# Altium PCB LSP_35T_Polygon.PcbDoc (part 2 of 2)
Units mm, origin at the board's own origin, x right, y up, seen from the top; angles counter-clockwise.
Board outline 152.4 x 101.6 mm, 4 copper layers (Top Layer, Mid-Layer 1, Mid-Layer 3, Bottom Layer); 138 components, 96 nets, 424 pads, 124 vias.
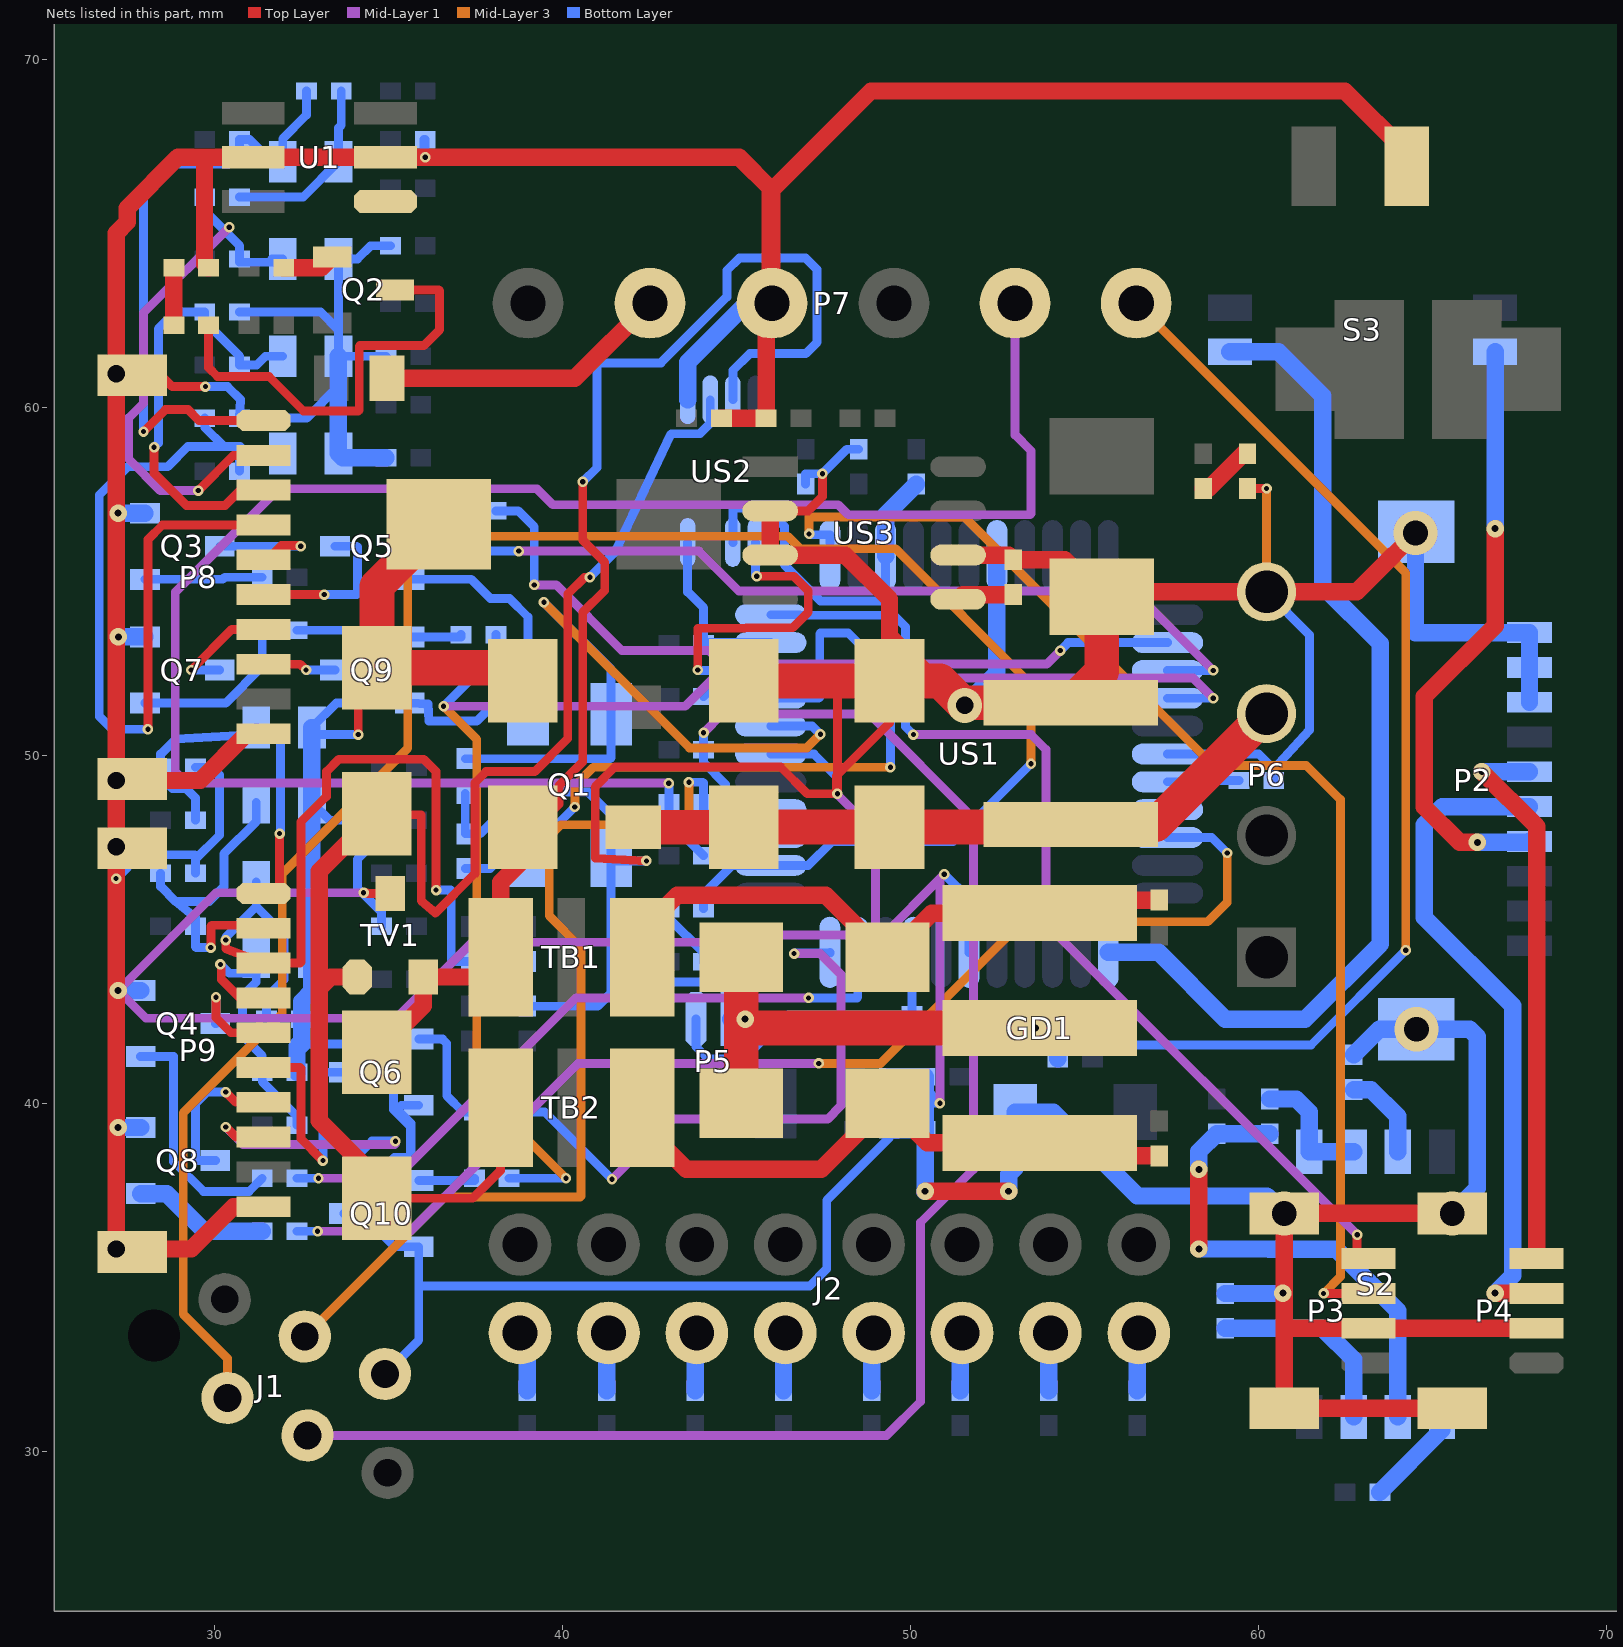
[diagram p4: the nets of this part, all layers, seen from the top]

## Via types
v1: diameter 0.3, hole 0.15, Top Layer to Bottom Layer, tented both sides, 95 vias
v2: diameter 0.5, hole 0.2, Top Layer to Bottom Layer, tented both sides, 20 vias
v3: diameter 1, hole 0.5, Top Layer to Bottom Layer, tented both sides, 5 vias
v4: diameter 1.27, hole 0.711, Top Layer to Bottom Layer, tented both sides, 4 vias

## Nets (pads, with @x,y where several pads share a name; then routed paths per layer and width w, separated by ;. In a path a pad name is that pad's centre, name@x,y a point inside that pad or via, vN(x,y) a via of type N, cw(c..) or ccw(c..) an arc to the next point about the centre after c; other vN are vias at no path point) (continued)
DO2: R34.2 US1.24 | length 22.4
  Mid-Layer 1 w0.254: v1(39.192,54.897) 39.826,54.897 41.714,53.01 44.222,53.01 44.611,52.621 53.916,52.621 v1(54.305,53.01)
  Bottom Layer w0.254: R34.2@38.092,57.023 38.735,57.023 39.192,56.566 v1(39.192,54.897) ; v1(54.305,53.01) 54.533,53.238 US1.24@57.389,53.238
DO3: R40.2 US1.25 | length 31
  Mid-Layer 1 w0.254: v1(38.748,55.867) 43.926,55.867 45.077,54.716 56.427,54.716 v1(58.706,52.438)
  Bottom Layer w0.254: R40.2@32.377,53.594 34.536,53.594 34.917,53.975 34.917,55.601 35.184,55.867 v1(38.748,55.867) ; US1.25@57.389,52.438 v1(58.706,52.438)
DO4: R46.2 R47.2 US1.26 | length 43.3
  Mid-Layer 1 w0.254: v1(36.589,51.41) 43.532,51.41 44.339,52.217 58.124,52.217 v1(58.703,51.638)
  Mid-Layer 3 w0.254: v1(36.589,51.41) 37.541,50.457 37.541,40.411 v1(40.107,37.846)
  Bottom Layer w0.254: v1(36.589,51.41) 38.092,52.913 R46.2@38.092,53.467 ; R47.2@38.473,37.846 v1(40.107,37.846) ; US1.26@57.389,51.638 v1(58.703,51.638)
DO5: R33.2 US1.43 | length 19.6
  Mid-Layer 1 w0.254: v1(32.995,37.846) 35.204,37.846 40.386,43.028 v1(47.075,43.028)
  Bottom Layer w0.254: R33.2@32.377,37.846 v1(32.995,37.846) ; v1(47.075,43.028) 48.464,43.028 48.489,43.053 US1.43@48.489,44.338
DO6: R36.2 US1.44 | length 17.6
  Mid-Layer 1 w0.254: v1(41.427,37.821) 43.155,39.548 47.625,39.548 48.006,39.929 48.006,43.709 47.411,44.303 v1(46.66,44.303)
  Bottom Layer w0.254: R36.2@38.473,39.751 39.497,39.751 v1(41.427,37.821) ; v1(46.66,44.303) 46.68,44.323 47.689,44.323 US1.44@47.689,44.338
DO7: R41.2 US1.31 | length 34
  Mid-Layer 1 w0.254: v1(32.969,36.322) 35.636,36.322 40.462,41.148 v1(47.371,41.148)
  Mid-Layer 3 w0.254: v1(47.371,41.148) 49.149,41.148 53.216,45.215 58.547,45.215 59.106,45.774 v1(59.106,47.193)
  Bottom Layer w0.254: R41.2@32.377,36.322 v1(32.969,36.322) ; US1.31@57.389,47.638 58.661,47.638 v1(59.106,47.193)
DO8: US1.30
GND: C1.2 C2.1 C3.1 C4.2 C5.2 C7.1 C9.1 C10.1 C11.2 C12.1 C13.2 C14.1 C15.1 C16.1 C17.1 C18.1 C19.1 C20.1 C21.1 C22.1 C23.1 C24.1 C25.1 C26.1 C27.1 C28.1 C29.1 CGND.1 D1.1 D2.2 D4.1 D6.1 D7.1 D8.1 D9.1 D10.1 D11.1 D12.1 D13.1 D14.1 D15.1 G1.2 GD1.3 J1.5 LED2.2 LED3.2 P2.8 P2.9 P2.10 P2.11 P2.12 P3.2 P3.Z1 P3.Z2 P4.2 P4.Z1 P4.Z2 P5.2 P6.4 P7.3 P8.10 P8.Z1 P8.Z2 P9.10 P9.Z1 P9.Z2 Q1.GND Q3.2 Q4.2 Q5.2 Q6.2 Q7.2 Q8.2 Q9.2 Q10.2 R7.1 R16.2 R17.2 R21.2 RGND.1 T1.2 TI1.2 TI2.2 TV1.3 U1.2 U1.5 US1.6 US1.18 US1.28 US1.39 US2.5 US3.2 US3.3 US3.6 | length 522
  Top Layer w0.254: 27.178,64.643 v3(27.178,60.96) 27.178,53.401 v3(27.178,49.276) v3(27.178,47.371) v1(27.178,46.457) 27.178,43.548 27.178,43.409 27.178,43.277 27.178,39.365 v2(27.239,39.304) ; v2@27.203,43.277 27.203,46.457 27.203,47.329 P9.Z1@27.645,47.329 ; v2(27.239,56.957) 27.203,56.993 27.203,60.918 P8.Z1@27.645,60.918 ; v2(27.244,53.401) 27.241,53.401 27.229,53.388 27.229,49.318 P8.Z2@27.645,49.318 ; P9.Z2@27.645,35.729 P9.Z2@28.118,35.729 ; P8.Z1@28.219,61.166 28.791,60.594 v1(29.743,60.594) ; 28.219,66.446 28.956,67.183 29.718,67.183 U1.5@31.12,67.183 U1.2@34.92,67.183 v1(36.06,67.183) 44.915,67.183 45.855,66.243 45.855,62.822 C9.1@45.855,59.69 ; 30.552,37.029 P9.10@31.42,37.029 ; v1(34.138,50.597) 34.138,51.752 34.523,52.138 D4.1@38.862,52.138 ; v1(34.29,46.05) 34.392,46.05 v1@34.411,46.031 ; v1@34.392,46.031 v1@34.411,46.031 ; TV1.3@35.052,46.031 v1@34.411,46.031 ; v1(42.418,46.965) 40.945,47.041 40.945,49.098 41.512,49.665 46.271,49.665 47.041,48.895 v1(47.904,48.895) 47.904,49.433 ; TI1.2@45.144,44.196 45.144,42.53 v2(45.256,42.418) ; D6.1@45.212,52.138 47.625,52.138 47.904,51.859 47.904,49.433 ; US3.2@45.974,57.023 47.066,57.023 47.473,57.429 v1(47.473,58.09) ; v1@47.879,48.895 47.879,49.408 47.904,49.433 ; 49.403,53.594 50.859,52.138 51.486,51.511 v3(51.562,51.435) ; 49.403,54.483 T1.2@49.403,52.138 49.403,50.932 47.904,49.433 ; LED2.2@59.69,57.666 v1(60.237,57.666) ; P3.Z1@60.745,31.236 60.745,33.528 60.753,33.536
  Top Layer w0.5: LED3.2@29.837,64.008 29.718,64.127 29.718,67.183 ; P9.10@31.42,37.029 30.552,37.029 29.337,35.814 v3(27.178,35.814) v3(27.178,47.371) v3(27.178,49.276) ; P8.10@31.42,50.618 30.933,50.618 29.591,49.276 v3(27.178,49.276) ; C10.1@44.569,59.69 C9.1@45.855,59.69 45.855,62.822 P7.3@46.025,62.992 46.025,66.243 ; US3.2@45.974,57.023 US3.3@45.974,55.753 48.133,55.753 49.403,54.483 T1.2@49.403,52.138 ; v2(50.427,37.473) v2(52.824,37.473) ; US3.6@51.374,55.753 52.824,55.753 C12.1@52.959,55.618 54.44,55.618 D7.1@55.499,54.559 55.636,54.697 P6.4@60.237,54.697 62.825,54.697 63.348,55.22 v4(64.516,56.388) ; 60.753,33.536 P3.2@63.17,33.536 P4.2@67.996,33.536 ; C13.2@64.262,66.929 64.262,67.31 62.484,69.088 48.87,69.088 46.025,66.243 ; P4.Z1@65.571,31.236 P3.Z1@60.745,31.236 v4(60.745,36.836) v4(65.571,36.836) ; v3(27.178,49.276) 27.178,53.401 v3(27.178,60.96) 27.178,65.006 27.497,65.324 27.497,65.724 28.956,67.183 29.718,67.183 ; 29.718,67.183 U1.5@31.12,67.183 U1.2@34.92,67.183 45.085,67.183 46.025,66.243
  Top Layer w1: C11.2@36.453,56.642 34.671,54.86 D2.2@34.671,52.519 38.481,52.519 D4.1@38.862,52.138 ; TI2.2@45.144,40.005 v2@45.144,42.291 ; TI1.2@45.144,44.196 v2@45.144,42.291 ; D6.1@45.212,52.138 T1.2@49.403,52.138 50.859,52.138 51.486,51.511 G1.2@54.61,51.511 55.499,52.4 D7.1@55.499,54.559 ; GD1.3@53.721,42.164 45.271,42.164 v2@45.144,42.291
  Mid-Layer 1 w0.254: v1(34.29,46.05) 30.048,46.05 v2(27.239,43.241) 28.037,42.443 35.23,42.443 37.414,44.628 45.994,44.628 46.2,44.834 48.784,44.834 ; v1@47.879,48.895 48.997,47.777 48.997,47.625 48.997,45.047 48.784,44.834 ; 48.641,44.834 48.784,44.834 ; v1(50.851,40.005) 50.851,45.771 50.851,46.457 ; v1(50.978,46.584) 50.851,46.457 ; 48.784,44.834 49.228,44.834 50.851,46.457
  Mid-Layer 3 w0.254: P6.4@60.237,54.697 v1(60.237,57.666)
  Bottom Layer w0.254: v1(27.178,46.457) 27.864,47.142 29.431,47.142 29.456,47.117 29.456,47.007 ; v2@27.203,43.277 v2(27.239,43.241) ; C18.1@29.456,46.609 29.456,47.007 ; C14.1@29.456,49.657 29.933,49.657 30.15,49.44 30.15,47.701 29.456,47.007 ; v1(29.743,60.594) 30.381,60.594 30.755,60.219 C28.1@30.726,59.69 32.652,59.69 33.566,60.604 D13.1@33.566,61.468 ; C24.1@30.726,62.738 33.058,62.738 33.566,62.23 ; C20.1@30.726,66.04 32.55,66.04 D9.1@33.566,67.056 D9.1@33.566,67.132 ; C26.1@32.377,40.894 32.377,41.381 32.703,41.707 34.493,41.707 35.154,41.046 35.154,39.818 35.631,39.34 35.631,38.506 35.573,38.448 ; D14.1@32.804,43.828 D14.1@32.804,44.196 D12.1@32.804,46.355 D10.1@32.804,48.641 33.312,48.133 C15.1@34.806,48.133 34.806,47.709 34.112,47.015 34.112,46.185 34.392,45.906 34.806,45.491 C19.1@34.806,45.085 ; C16.1@33.647,69.088 33.647,68.102 33.566,68.021 D9.1@33.566,67.132 ; v1(34.138,50.597) 32.804,50.597 D8.1@32.804,50.8 33.505,51.501 Q9.2@35.619,51.501 36.144,51.476 36.17,50.983 37.544,50.983 37.971,51.41 Q1.GND@39.014,51.41 ; J1.5@34.902,32.223 35.873,33.194 35.873,34.747 ; C25.1@34.933,61.468 D13.1@33.566,61.468 ; C21.1@35.06,64.643 34.493,64.643 34.112,64.262 D11.1@33.566,64.262 33.566,62.23 ; Q5.2@35.619,55.057 37.384,55.057 37.932,54.508 38.481,54.508 39.014,53.975 Q1.GND@39.014,51.41 ; Q6.2@35.873,39.944 35.843,39.944 35.382,39.944 35.281,39.842 35.281,39.792 35.648,39.424 35.648,38.506 35.59,38.448 35.573,38.448 ; v1(36.06,67.183) C17.1@36.06,67.691 36.017,67.691 36.017,67.158 35.992,67.132 D9.1@33.566,67.132 ; C2.1@37.211,48.903 C3.1@37.211,47.744 37.643,47.744 38.84,48.941 40.746,48.941 41.402,48.285 Q1.GND@41.402,47.117 Q1.GND@41.402,46.965 ; C23.1@38.989,44.077 C27.1@38.989,42.791 39.878,42.791 41.013,42.791 41.402,43.18 41.402,43.485 ; Q1.GND@39.014,51.181 Q1.GND@39.014,51.41 ; v1(42.418,46.965) Q1.GND@41.402,46.965 ; P5.2@44.839,42.418 44.839,43.459 44.814,43.485 41.402,43.485 ; US1.6@45.989,50.038 47.228,50.038 47.904,49.362 v1(47.904,48.895) ; C7.1@46.99,57.793 46.99,58.09 v1(47.473,58.09) 48.176,58.793 R21.2@48.514,58.793 ; C4.2@49.395,40.767 49.395,40.322 ; C5.2@50.427,40.767 50.427,40.429 v1(50.851,40.005) 49.713,40.005 49.395,40.322 ; v1(50.978,46.584) 51.689,45.872 US1.39@51.689,44.338 ; US1.28@57.389,50.038 60.008,50.038 60.444,49.601 ; P6.4@60.237,54.697 61.468,53.465 61.468,50.724 60.444,49.601 ; C1.2@60.444,49.276 60.444,49.601 ; D13.1@33.566,61.468 33.566,62.23 ; 35.573,38.448 35.179,38.448 34.798,38.067 34.798,36.261 35.179,35.88 Q10.2@35.873,35.88 35.873,34.747 ; 35.873,34.747 47.104,34.747 47.6,35.242 47.6,37.211 49.395,39.006 R16.2@49.395,39.243 49.395,40.322 ; 41.402,43.485 Q1.GND@41.402,46.965
  Bottom Layer w0.5: v2(27.239,39.304) Q8.2@27.881,39.304 ; v2(27.239,43.241) Q4.2@27.881,43.241 ; v2(27.239,56.957) Q3.2@28.008,56.957 ; v2(27.244,53.401) Q7.2@28.008,53.401 ; C26.1@32.377,40.894 32.377,41.648 32.512,41.783 32.512,42.926 32.804,43.218 D8.1@32.804,50.8 ; D13.1@33.566,61.468 D15.1@33.566,58.674 33.693,58.547 C29.1@34.933,58.547 ; US2.5@43.602,60.216 43.602,61.3 45.294,62.992 P7.3@46.025,62.992 ; P5.2@44.839,42.418 v2(45.256,42.418) ; R16.2@49.395,39.243 R17.2@50.427,39.243 ; C4.2@49.395,40.767 C5.2@50.427,40.767 R17.2@50.427,39.243 ; v2@50.419,37.465 v2(50.427,37.473) R17.2@50.427,39.243 ; v3(51.562,51.435) 52.489,52.362 US1.18@52.489,55.738 ; v2(52.824,37.473) 52.824,37.965 53.012,38.153 D1.1@53.012,39.751 54.102,39.751 56.515,37.338 60.243,37.338 v4(60.745,36.836) ; v2(53.594,42.164) 54.237,41.521 R7.1@54.237,41.275 ; RGND.1@59.055,34.536 60.698,34.536 v2(60.706,34.544) ; CGND.1@62.738,41.394 63.47,42.126 v4(64.542,42.126) 66.078,42.126 66.294,41.91 66.294,37.559 v4(65.571,36.836) ; v4(64.516,56.388) 64.516,53.526 P2.10@67.792,53.526 P2.9@67.792,52.526 P2.8@67.792,51.526
LD1: P8.5 Q3.1 | length 3.6
  Top Layer w0.254: P8.5@31.42,55.618 31.521,55.618 31.936,56.032 32.461,56.032 v1(32.487,56.007)
  Bottom Layer w0.254: Q3.1@30.158,56.007 v1(32.487,56.007)
LD2: P8.6 Q5.1 | length 4.7
  Top Layer w0.254: P8.6@31.42,54.618 v1(33.158,54.618)
  Bottom Layer w0.254: v1(33.158,54.618) 34.087,54.618 34.112,54.643 34.112,55.982 34.087,56.007 Q5.1@33.469,56.007
LD3: P8.7 Q7.1 | length 3.4
  Top Layer w0.254: v1(29.337,52.451) 30.504,53.618 P8.7@31.42,53.618
  Bottom Layer w0.254: v1(29.337,52.451) Q7.1@30.158,52.451
LD4: P8.8 Q9.1 | length 2.1
  Top Layer w0.254: P8.8@31.42,52.618 32.472,52.618 v1(32.639,52.451)
  Bottom Layer w0.254: v1(32.639,52.451) Q9.1@33.469,52.451
LD5: P9.5 Q4.1 | length 2.9
  Top Layer w0.254: v1(30.048,43.045) 30.048,42.461 30.48,42.029 P9.5@31.42,42.029
  Bottom Layer w0.254: Q4.1@30.031,42.291 30.048,42.291 v1(30.048,43.045)
LD6: P9.6 Q6.1 | length 7.1
  Top Layer w0.254: P9.6@31.42,41.029 32.461,41.029 32.487,41.004 32.487,38.989 v1(33.122,38.354)
  Bottom Layer w0.254: v1(33.122,38.354) 33.122,40.869 33.147,40.894 Q6.1@33.723,40.894
LD7: P9.7 Q8.1 | length 4.4
  Top Layer w0.254: v1(30.328,40.322) 30.621,40.029 P9.7@31.42,40.029
  Bottom Layer w0.254: Q8.1@30.031,38.354 29.489,38.354 29.464,38.379 29.464,40.005 29.781,40.322 v1(30.328,40.322)
LD8: P9.8 Q10.1 | length 9.7
  Top Layer w0.254: v1(30.328,39.319) 30.342,39.319 30.632,39.029 P9.8@31.42,39.029
  Mid-Layer 1 w0.254: v1(30.328,39.319) 30.829,38.818 35.179,38.818 35.204,38.843 v1(35.204,38.913)
  Bottom Layer w0.254: Q10.1@33.723,36.83 34.036,36.83 34.036,38.417 34.531,38.913 v1(35.204,38.913)
MISO: J1.2 LED1.2 US1.2 | length 61
  Mid-Layer 3 w0.254: J1.2@30.376,31.531 30.376,32.675 29.108,33.943 29.108,39.726 31.953,42.57 31.953,46.596 35.56,50.203 35.56,55.778 36.076,56.294 46.474,56.294 46.833,55.936 49.576,55.936 53.467,52.045 v1(53.467,49.759)
  Bottom Layer w0.254: LED1.2@44.061,45.593 44.061,46.017 44.882,46.838 US1.2@45.989,46.838 47.067,46.838 47.752,47.523 51.232,47.523 v1(53.467,49.759)
NetC1_1: C1.1 US1.29 | length 2.1
  Bottom Layer w0.254: US1.29@57.389,49.238 58.395,49.238 58.433,49.276 C1.1@59.444,49.276
NetC2_2: C2.2 Q1.2 US1.7 | length 20.8
  Mid-Layer 3 w0.254: v1(39.472,54.398) 43.655,50.214 47.026,50.214 v1(47.415,50.603)
  Bottom Layer w0.254: C2.2@37.211,49.903 41.377,49.903 41.402,49.928 Q1.2@41.402,51.181 41.402,52.468 v1(39.472,54.398) ; US1.7@45.989,50.838 47.181,50.838 v1(47.415,50.603)
NetC3_2: C3.2 Q1.1 US1.8 | length 22.7
  Mid-Layer 3 w0.254: v1(40.361,48.514) 40.361,49.124 40.894,49.657 v1(49.428,49.657)
  Bottom Layer w0.254: C3.2@37.211,46.744 37.922,46.744 38.295,47.117 Q1.1@39.014,47.117 39.014,47.879 39.726,47.879 v1(40.361,48.514) ; US1.8@45.989,51.638 47.371,51.638 47.396,51.663 47.396,53.492 47.422,53.518 48.208,53.518 49.428,52.297 v1(49.428,49.657)
NetC12_2: C12.2 US3.5 | length 1.6
  Top Layer w0.5: US3.5@51.374,54.483 51.509,54.618 C12.2@52.959,54.618
NetCGND_2: CGND.2 S2.7 | length 2.6
  Bottom Layer w0.5: CGND.2@62.738,40.394 63.238,40.394 64.008,39.624 S2.7@64.008,38.608
NetD2_1: D2.1 D3.1 TB2.1 TV1.1 US2.6 | length 42.7
  Top Layer w0.254: D3.1@34.671,37.27 37.423,37.27 38.227,38.074 TB2.1@38.227,39.878 ; D2.1@34.671,48.319 35.946,48.289 35.946,45.819 36.35,45.466 37.49,46.607 37.49,49.212 37.808,49.53 39.205,49.53 40.157,50.482 40.157,54.635 40.64,55.118 v1(40.792,55.118)
  Top Layer w0.5: TV1.1@34.102,43.631 33.344,43.631 33.02,43.307 ; D3.1@34.671,37.27 34.671,37.846 33.02,39.497 33.02,43.307 ; D2.1@34.671,48.319 33.02,46.668 33.02,43.307
  Bottom Layer w0.254: v1(40.792,55.118) 41.508,55.834 43.129,59.239 43.953,59.239 44.252,59.538 US2.6@44.252,60.216
NetD3_2: D3.2 D4.2 TB1.1 TV1.2 US2.7 | length 38
  Top Layer w0.254: D4.2@38.862,47.938 39.243,47.938 39.901,48.596 39.901,49.121 40.589,49.809 40.589,54.107 41.219,54.737 41.219,55.545 40.589,56.175 v1(40.589,57.861)
  Top Layer w0.5: D3.2@34.671,41.47 36.002,42.801 TV1.2@36.002,43.631 37.662,43.631 TB1.1@38.227,44.196 38.227,46.355 38.862,46.99 D4.2@38.862,47.938
  Bottom Layer w0.254: v1(40.589,57.861) 40.996,58.268 40.996,61.277 42.834,61.277 44.729,63.173 44.729,63.932 45.085,64.287 46.99,64.287 47.32,63.957 47.32,61.874 46.99,61.544 45.39,61.544 44.902,61.056 US2.7@44.902,60.216
NetD5_1: D5.1 D6.2 G1.1 P6.3 T1.1 | length 19.5
  Top Layer w1: D5.1@42.037,47.932 D6.2@45.206,47.932 ; D6.2@45.212,47.938 T1.1@49.403,47.938 54.542,47.938 G1.1@54.61,48.006 57.046,48.006 P6.3@60.237,51.197
NetF1_2: F1.2 P7.2 | length 8.5
  Top Layer w0.5: F1.2@34.963,60.833 40.361,60.833 P7.2@42.52,62.992
NetGD1_1: GD1.1 R22.1 TB1.2 TI1.1 | length 17.5
  Top Layer w0.5: TB1.2@42.291,44.196 42.291,44.958 43.307,45.974 47.566,45.974 TI1.1@49.344,44.196 50.614,45.466 GD1.1@53.721,45.466 54.094,45.839 R22.1@57.15,45.839
NetGD1_2: GD1.2 R23.1 TB2.2 TI2.1 | length 17.3
  Top Layer w0.5: TB2.2@42.291,39.878 42.291,39.37 43.561,38.1 47.439,38.1 TI2.1@49.344,40.005 50.487,38.862 GD1.2@53.721,38.862 54.094,38.489 R23.1@57.15,38.489
NetJ2_1: J2.1 R8.2 | length 1.7
  Bottom Layer w0.5: J2.1@38.786,33.401 38.989,33.198 R8.2@38.989,31.742
NetJ2_2: J2.2 R9.2 | length 1.7
  Bottom Layer w0.5: R9.2@41.275,31.742 41.275,33.35 J2.2@41.326,33.401
NetJ2_3: J2.3 R10.2 | length 1.7
  Bottom Layer w0.5: R10.2@43.815,31.742 43.815,33.35 J2.3@43.866,33.401
NetJ2_4: J2.4 R11.2 | length 1.7
  Bottom Layer w0.5: R11.2@46.355,31.742 46.355,33.35 J2.4@46.406,33.401
NetJ2_5: J2.5 R12.2 | length 1.7
  Bottom Layer w0.5: R12.2@48.895,31.742 48.895,33.35 J2.5@48.946,33.401
NetJ2_6: J2.6 R13.2 | length 1.7
  Bottom Layer w0.5: R13.2@51.435,31.742 51.435,33.35 J2.6@51.486,33.401
NetJ2_7: J2.7 R14.2 | length 1.7
  Bottom Layer w0.5: R14.2@53.975,31.742 53.975,33.35 J2.7@54.026,33.401
NetJ2_8: J2.8 R15.2 | length 1.7
  Bottom Layer w0.5: R15.2@56.515,31.742 56.515,33.35 J2.8@56.566,33.401
NetLED1_1: LED1.1 R3.2 | length 1.9
  Bottom Layer w0.254: LED1.1@43.061,45.593 43.061,45.323 44.061,44.323 R3.2@44.061,44.069
NetLED2_1: LED2.1 R24.2 | length 1.7
  Top Layer w0.5: R24.2@58.42,57.666 58.574,57.666 59.574,58.666 LED2.1@59.69,58.666
NetLED3_1: LED3.1 R27.1 | length 1.7
  Top Layer w0.254: R27.1@28.837,62.357 28.837,62.619
  Top Layer w0.5: 28.837,62.619 LED3.1@28.837,64.008
NetP2_4: P2.4 S3.2 | length 17.4
  Top Layer w0.5: v2(66.294,47.498) 65.786,47.498 64.77,48.514 64.77,51.689 66.802,53.721 v2(66.802,56.515)
  Bottom Layer w0.5: v2(66.294,47.498) 67.764,47.498 P2.4@67.792,47.526 ; v2(66.802,56.515) S3.2@66.802,61.595
NetP7_5: P7.5 R4.1 R5.2 | length 54.4
  Mid-Layer 1 w0.254: v1(43.061,49.2) 29.21,49.2 28.88,49.53 28.88,54.688 31.85,57.658 39.268,57.658 39.728,57.198 47.931,57.198 48.215,56.913 53.442,56.913 53.467,56.939 53.467,58.75 53.01,59.207 P7.5@53.01,62.992
  Bottom Layer w0.254: v1(43.061,49.2) R5.2@43.061,48.641 43.061,48.117 R4.1@44.061,47.117
NetP7_6: P7.6 R6.2 | length 32.2
  Mid-Layer 3 w0.254: P7.6@56.49,62.992 64.237,55.245 v1(64.237,44.399)
  Bottom Layer w0.254: R6.2@55.872,42.545 55.872,41.677 61.514,41.677 v1(64.237,44.399)
NetQ2_1: Q2.1 R26.2 | length 1.5
  Top Layer w0.5: R26.2@31.996,64.008 33.075,64.008 Q2.1@33.39,64.323
NetQ2_3: Q2.3 R27.2 | length 12.8
  Top Layer w0.254: R27.2@29.837,62.357 29.837,61.138 30.091,60.884 31.572,60.884 32.563,59.893 34.138,59.893 34.163,59.919 34.163,61.747 34.188,61.773 36.017,61.773 36.474,62.23 36.474,63.348 36.449,63.373 Q2.3@35.19,63.373
NetQ3_3: Q3.3 R32.1 | length 3.4
  Bottom Layer w0.254: Q3.3@28.008,55.057 30.242,55.057 30.303,55.118 R32.1@31.377,55.118
NetQ4_3: Q4.3 R33.1 | length 7
  Bottom Layer w0.254: Q4.3@27.881,41.341 28.829,41.341 28.829,38.329 29.693,37.465 30.996,37.465 R33.1@31.377,37.846
NetQ5_3: Q5.3 R34.1 | length 1.5
  Bottom Layer w0.254: Q5.3@35.619,56.957 36.322,56.957 36.388,57.023 R34.1@37.092,57.023
NetQ6_3: Q6.3 R36.1 | length 3.3
  Bottom Layer w0.254: Q6.3@35.873,41.844 36.554,41.844 36.678,41.72 36.678,40.221 37.148,39.751 R36.1@37.473,39.751
NetQ7_3: Q7.3 R40.1 | length 4.8
  Bottom Layer w0.254: Q7.3@28.008,51.501 30.325,51.501 31.377,52.553 R40.1@31.377,53.594
NetQ8_3: Q8.3 R41.1 | length 3.9
  Bottom Layer w0.5: Q8.3@27.881,37.404 28.636,37.404 29.718,36.322 R41.1@31.377,36.322
NetQ9_3: Q9.3 R46.1 | length 1.5
  Bottom Layer w0.254: Q9.3@35.619,53.401 37.092,53.401 R46.1@37.092,53.467
NetQ10_3: Q10.3 R47.1 | length 1.7
  Bottom Layer w0.254: Q10.3@35.873,37.78 37.473,37.78 R47.1@37.473,37.846
NetR12A_2: R12A.2 R12B.2 S2.2 | length 14.5
  Top Layer w0.5: v2(58.293,35.814) v2(58.293,38.1)
  Bottom Layer w0.5: v2(58.293,35.814) 60.303,35.814 60.316,35.801 62.243,35.801 64.008,34.036 S2.2@64.008,30.988 ; v2(58.293,38.1) 58.293,38.616 R12A.2@58.801,39.124 R12B.2@60.325,39.124
NetR12B_1: R12B.1 S2.5 S2.6 | length 3.7
  Bottom Layer w0.5: R12B.1@60.325,40.124 61.095,40.124 61.468,39.751 S2.5@61.468,38.608 S2.6@62.738,38.608
NetRGND_2: RGND.2 S2.3 | length 5.7
  Bottom Layer w0.5: RGND.2@59.055,33.536 61.841,33.536 62.738,32.639 S2.3@62.738,30.988
NetRVCC_2: RVCC.2 S2.1 | length 2.9
  Bottom Layer w0.5: RVCC.2@63.492,28.829 65.278,30.615 S2.1@65.278,30.988
PRESS: S3.1 US1.34 | length 29.1
  Bottom Layer w0.5: US1.34@55.689,44.338 57.135,44.338 59.055,42.418 61.341,42.418 63.5,44.577 63.5,47.498 63.5,53.213 61.849,54.864 61.849,60.325 60.579,61.595 S3.1@59.182,61.595
RE: R20.1 US1.14 US2.2 | length 10.8
  Bottom Layer w0.254: US2.2@44.902,56.116 44.902,57.074 44.927,57.099 45.864,57.099 46.38,56.582 46.38,55.474 47.422,54.432 49.264,54.432 49.289,54.458 US1.14@49.289,55.738
  Bottom Layer w0.5: US1.14@49.289,55.738 49.289,56.917 R20.1@50.165,57.793
RST: J1.4 R1.1 US1.4 | length 48.3
  Mid-Layer 1 w0.254: J1.4@32.678,30.458 49.317,30.458 50.292,31.432 50.292,36.576 51.816,38.1 51.816,48.188 48.815,51.189 44.602,51.189 v1(44.061,50.648)
  Bottom Layer w0.254: v1(44.061,50.648) R1.1@44.061,50.165 44.061,49.792 44.687,49.166 44.687,48.658 44.907,48.438 US1.4@45.989,48.438
RXD0: R18.2 US1.9 US2.1 | length 11
  Top Layer w0.254: v1(43.891,52.451) 43.891,53.645 46.622,53.67 47.066,54.115 47.066,54.724 46.647,55.143 v1(45.587,55.143)
  Bottom Layer w0.254: v1(43.891,52.451) 43.904,52.438 44.81,52.438 ; R18.2@44.061,51.689 44.81,52.438 ; US2.1@45.552,56.116 45.552,55.179 v1(45.587,55.143) ; US1.9@45.989,52.438 44.81,52.438
RXD1: P2.6 P4.4 | length 16
  Top Layer w0.5: v2(66.421,49.53) 67.996,47.955 67.996,44.399 67.996,36.525 P4.4@67.996,35.536
  Bottom Layer w0.5: v2@66.425,49.526 P2.6@67.792,49.526
RXD2: P3.4 US1.11 | length 29.9
  Top Layer w0.254: v1(62.84,36.22) 62.84,35.536 P3.4@63.17,35.536
  Mid-Layer 1 w0.254: v1(50.089,50.597) 53.467,50.597 53.899,50.165 53.899,45.161 v1(62.84,36.22)
  Bottom Layer w0.254: US1.11@45.989,54.038 46.812,54.038 46.812,54.026 49.53,54.026 49.86,53.696 49.86,50.825 v1(50.089,50.597)
S1: C16.2 D9.2 P8.1 R31.1 | length 18.1
  Top Layer w0.254: v1(27.965,59.301) 28.597,59.932 29.246,59.932 29.561,59.618 P8.1@31.42,59.618
  Bottom Layer w0.254: v1(27.965,59.301) 27.965,66.04 28.918,66.992 30.409,66.992 30.726,67.31 R31.1@30.726,67.691 31.013,67.691 31.648,67.056 D9.2@31.966,67.056 31.966,67.716 32.647,68.397 C16.2@32.647,69.088
S2: C20.2 D11.2 P8.2 R39.1 | length 16.3
  Top Layer w0.254: v1(29.54,57.607) 30.551,58.618 P8.2@31.42,58.618
  Mid-Layer 1 w0.254: v1(29.54,57.607) 28.448,57.607 27.534,58.522 27.534,59.69 27.965,60.122 27.965,62.713 v1(30.429,65.176)
  Bottom Layer w0.254: C20.2@29.726,66.04 29.726,65.643 30.311,65.058 ; v1(30.429,65.176) 30.311,65.058 ; D11.2@31.966,64.262 31.657,64.262 31.657,64.168 30.726,64.168 R39.1@30.726,64.262 30.726,64.643 30.311,65.058
S3: C24.2 D13.2 P8.3 R45.1 | length 12.7
  Top Layer w0.254: v1(28.27,58.852) 28.27,58.102 29.193,57.18 30.311,57.18 30.749,57.618 P8.3@31.42,57.618
  Bottom Layer w0.254: v1(28.27,58.852) 28.392,58.974 28.392,62.253 28.877,62.738 C24.2@29.726,62.738 29.726,62.468 30.726,61.468 R45.1@30.726,61.214 31.217,61.214 31.471,61.468 D13.2@31.966,61.468
S4: C28.2 D15.2 P8.4 R51.1 | length 24.5
  Top Layer w0.254: v1(28.092,50.749) 28.092,56.197 28.513,56.618 P8.4@31.42,56.618
  Bottom Layer w0.254: v1(28.092,50.749) 27.064,50.749 26.695,51.117 26.695,57.48 27.508,58.293 28.66,58.293 29.244,58.877 30.269,58.877 ; C28.2@29.726,59.69 29.726,59.42 30.269,58.877 ; R51.1@30.726,58.166 30.726,58.345 30.726,58.869 ; D15.2@31.966,58.674 31.055,58.674 30.937,58.674 30.734,58.877 30.269,58.877
S5: C14.2 D8.2 P9.1 R30.1 | length 11.4
  Top Layer w0.254: P9.1@31.42,46.029 31.877,46.029 v1(31.877,47.752)
  Bottom Layer w0.254: R30.1@29.456,48.133 29.456,48.782 29.196,49.043 28.8,49.043 28.456,49.387 C14.2@28.456,49.657 28.456,50.033 28.892,50.47 D8.2@31.204,50.597 ; D8.2@31.204,50.8 D8.2@31.204,50.597 ; v1(31.877,47.752) 31.902,47.777 31.902,50.571 31.877,50.597 D8.2@31.204,50.597
S6: C18.2 D10.2 P9.2 R38.1 | length 9.6
  Top Layer w0.254: v1(29.901,44.475) 29.901,45.085 29.932,45.116 30.755,45.116 30.755,45.029 P9.2@31.42,45.029
  Bottom Layer w0.254: C18.2@28.456,46.609 28.456,46.233 28.892,45.796 ; v1(29.901,44.475) 29.481,44.475 29.456,44.501 R38.1@29.456,45.085 29.456,45.339 28.892,45.796 ; D10.2@31.204,48.641 31.204,48.095 30.277,47.168 30.277,46.228 29.845,45.796 28.892,45.796
S7: C22.2 D12.2 P9.3 R44.1 | length 23.9
  Top Layer w0.254: v1(30.328,44.689) 30.328,44.44 P9.3@31.42,44.029 32.461,44.029 32.487,44.054 32.487,48.082 33.223,48.819 33.223,49.53 33.579,49.886 36.017,49.886 36.373,49.53 v1(36.373,46.126)
  Bottom Layer w0.254: v1(30.328,44.689) 30.328,44.767 31.204,45.656 ; D12.2@31.204,46.355 31.204,45.656 ; C22.2@31.504,42.418 31.504,43.053 32.004,43.553 32.004,44.856 31.204,45.656 ; v1(36.373,46.126) 36.786,46.126 36.811,46.101 36.811,44.12 36.854,44.077 R44.1@37.338,44.077
S8: C26.2 D14.2 P9.4 R50.1 | length 8.7
  Top Layer w0.254: v1(30.175,43.993) 30.188,43.993 30.201,43.98 30.201,43.562 30.734,43.029 P9.4@31.42,43.029
  Bottom Layer w0.254: v1(30.175,43.993) 30.429,43.739 D14.2@31.204,43.739 ; D14.2@31.204,44.196 D14.2@31.204,43.739 ; R50.1@32.377,39.37 32.377,39.624 31.377,40.624 C26.2@31.377,40.894 31.377,41.369 30.81,41.935 30.81,43.091 31.204,43.485 D14.2@31.204,43.739
SCK: J1.3 R5.1 US1.3 | length 29
  Mid-Layer 3 w0.254: J1.3@32.6,33.296 36.616,37.313 40.513,37.313 40.538,37.338 40.538,44.475 39.624,45.39 39.624,47.676 39.954,48.006 43.383,48.006 43.637,48.26 v1(43.637,49.225)
  Bottom Layer w0.254: v1(43.637,49.225) 44.036,49.225 44.061,49.2 R5.1@44.061,48.641 44.061,48.395 44.818,47.638 US1.3@45.989,47.638
SHT_C: P5.1 R2.2 US1.41 | length 9.5
  Bottom Layer w0.254: P5.1@43.839,42.418 43.839,41.632 44.196,41.275 45.212,41.275 46.482,42.545 R2.2@50.046,42.545 50.046,44.279 US1.41@50.038,44.287
  Bottom Layer w0.5: US1.41@50.038,44.287 US1.41@50.089,44.338
SHT_D: U1.1
TXD0: R19.2 US1.10 US2.4 | length 5
  Bottom Layer w0.254: US2.4@43.602,56.116 43.602,54.696 44.061,54.237 R19.2@44.061,53.213 44.086,53.238 US1.10@45.989,53.238
TXD1: P2.5 P4.3 | length 19.2
  Top Layer w0.5: v2(66.802,34.544) 67.988,34.544 P4.3@67.996,34.536
  Bottom Layer w0.5: v2(66.802,34.544) 67.31,35.052 67.31,42.799 64.77,45.339 64.77,48.006 65.29,48.526 P2.5@67.792,48.526
TXD2: P3.3 US1.12 | length 36
  Top Layer w0.254: v1(61.874,34.536) P3.3@63.17,34.536
  Mid-Layer 3 w0.254: v1(47.092,56.363) 47.092,56.845 51.562,56.845 58.699,49.708 61.379,49.708 62.357,48.73 62.357,35.019 v1(61.874,34.536)
  Bottom Layer w0.254: v1(47.092,56.363) 47.117,56.337 47.689,56.337 US1.12@47.689,55.738
pads on no net: J1. P2.7 P5.Z1 P5.Z2 S3.3 S3.4 TB1.0 TB2.0 U1.3 U1.4 US1.15 US1.16 US1.40

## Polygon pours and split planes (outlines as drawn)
GND on Top Layer "Top Layer-No Net" (solid, pour order 2): 26.543,63.754 27.686,63.754 33.528,69.596 61.849,69.596 62.992,69.596 68.834,63.754 68.834,33.147 67.945,33.147 62.23,27.432 62.103,27.559 33.401,27.559 32.385,27.559 26.543,33.401

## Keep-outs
Keep-Out Layer:
  lines w0.127: 69.127,39.244 69.127,57.659 ; 26.327,33.951 ccw(c33.227,33.951) 33.227,27.051 62.227,27.051 ccw(c62.227,33.951) 69.127,33.951 69.127,62.951 ccw(c62.227,62.951) 62.227,69.851 33.227,69.851 ccw(c33.227,62.951) 26.327,62.951 26.327,33.951

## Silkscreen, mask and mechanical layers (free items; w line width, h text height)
Top Overlay:
  text "1-W" at 39.548,65.151 h1.52 r90
  text "5V" at 43.104,65.151 h1.52 r90
  text "GND" at 46.787,65.151 h1.52 r90
  text "12V" at 50.343,65.151 h1.52 r90
  text "B" at 53.772,65.151 h1.52 r90
  text "A" at 57.074,65.151 h1.52 r90
Mechanical 1:
  lines w0.127: 69.127,39.244 69.127,57.659 ; 26.327,33.951 ccw(c33.227,33.951) 33.227,27.051 62.227,27.051 ccw(c62.227,33.951) 69.127,33.951 69.127,62.951 ccw(c62.227,62.951) 62.227,69.851 33.227,69.851 ccw(c33.227,62.951) 26.327,62.951 26.327,33.951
